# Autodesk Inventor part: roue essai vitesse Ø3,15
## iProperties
Created: 2011-11
Part Number: roue essai vitesse Ø3,15
Document SubType Name: Modeling
Designer: Laur
Density: 1 g/cm^3
Author: Laur
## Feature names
1. Extrusion1
2. Extrusion2
3. Extrusion3
